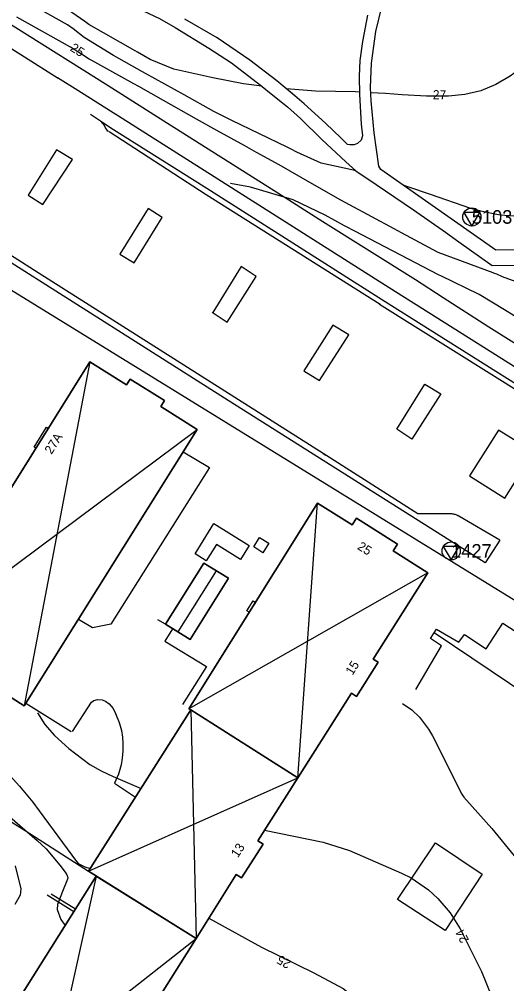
# Model space of a CAD drawing. Extents: x 67169 to 69652, y 20189 to 22818.
# Drawn here: x 69308.9 to 69362.6, y 21145.5 to 21251.9 of the extents above; entities that cross this region are included whole.
import ezdxf

# ---------------------------------------------------------------- set-up
doc = ezdxf.new("R2010")
doc.units = 0
for name, color, linetype in [('BYGGNAD_HUSLIV', 7, 'Continuous'), ('BYGGNAD_HUSLIV 11', 7, 'Continuous'), ('BYGGNAD_HUSLIV 13', 7, 'Continuous'), ('BYGGNADSDETALJER', 7, 'Continuous'), ('BYGGNADSSYMBOLER', 7, 'Continuous'), ('BYGGNADSSYMBOLER 30', 7, 'Continuous'), ('HOJDKURVOR_2014', 7, 'Continuous'), ('HOJDKURVOR_2014 5M', 7, 'Continuous'), ('HOJDKURVOR_TEXTER_2014', 7, 'Continuous'), ('Instruktioner', 7, 'Continuous'), ('MUR_STAKET', 7, 'Continuous'), ('MUR_STAKET_SYMBOL', 7, 'Continuous'), ('Std_Ritningsstämpel', 7, 'Continuous'), ('STOMPUNKTER', 7, 'Continuous'), ('STOMPUNKTER TEXT', 7, 'Continuous'), ('VAGAR 121', 7, 'Continuous'), ('VAGAR 123', 7, 'Continuous')]:
    doc.layers.add(name, color=color, linetype=linetype)

msp = doc.modelspace()

# ---------------------------------------------------------------- linework, layer by layer
at = {"layer": 'BYGGNAD_HUSLIV'}
for points in [[(69316.67, 21214.12), (69320.72, 21211.55), (69321.12, 21212.18), (69324.91, 21209.84), (69324.48, 21209.17), (69328.5, 21206.63), (69309.43, 21176.14), (69305.4, 21178.7), (69304.99, 21178.06), (69301.22, 21180.45), (69301.63, 21181.08), (69297.6, 21183.63), (69316.67, 21214.12)], [(69341.78, 21198.52), (69345.6, 21196.11), (69346.07, 21196.85), (69350.59, 21194), (69350.12, 21193.25), (69353.96, 21190.82), (69347.92, 21181.31), (69348.48, 21180.95), (69346.09, 21177.18), (69345.53, 21177.53), (69339.59, 21168.19), (69327.59, 21175.83), (69341.78, 21198.52)], [(69329.25, 21191.9), (69331.97, 21190.22), (69327.73, 21183.46), (69325.01, 21185.14), (69329.25, 21191.9)], [(69327.79, 21175.7), (69339.59, 21168.19), (69335.19, 21161.25), (69335.78, 21160.88), (69333.4, 21157.16), (69332.8, 21157.53), (69328.38, 21150.49), (69316.52, 21157.9), (69327.79, 21175.7)], [(69354.78, 21161.03), (69359.95, 21157.59), (69355.85, 21151.37), (69350.59, 21154.77), (69354.78, 21161.03)], [(69317.37, 21157.37), (69328.38, 21150.49), (69309.01, 21119.71), (69298, 21126.59), (69317.37, 21157.37)]]:
    msp.add_lwpolyline(points, dxfattribs=at)
at = {"layer": 'BYGGNAD_HUSLIV 11'}
for points in [[(69316.67, 21214.12), (69320.72, 21211.55), (69321.12, 21212.18), (69324.91, 21209.84), (69324.48, 21209.17), (69328.5, 21206.63), (69309.43, 21176.14), (69305.4, 21178.7), (69304.99, 21178.06), (69301.22, 21180.45), (69301.63, 21181.08), (69297.6, 21183.63), (69316.67, 21214.12)], [(69341.78, 21198.52), (69345.6, 21196.11), (69346.07, 21196.85), (69350.59, 21194), (69350.12, 21193.25), (69353.96, 21190.82), (69347.92, 21181.31), (69348.48, 21180.95), (69346.09, 21177.18), (69345.53, 21177.53), (69339.59, 21168.19), (69327.59, 21175.83), (69341.78, 21198.52)], [(69327.79, 21175.7), (69339.59, 21168.19), (69335.19, 21161.25), (69335.78, 21160.88), (69333.4, 21157.16), (69332.8, 21157.53), (69328.38, 21150.49), (69316.52, 21157.9), (69327.79, 21175.7)], [(69317.37, 21157.37), (69328.38, 21150.49), (69309.01, 21119.71), (69298, 21126.59), (69317.37, 21157.37)]]:
    msp.add_lwpolyline(points, dxfattribs=at)
at = {"layer": 'BYGGNAD_HUSLIV 13'}
msp.add_lwpolyline([(69354.78, 21161.03), (69359.95, 21157.59), (69355.85, 21151.37), (69350.59, 21154.77), (69354.78, 21161.03)], dxfattribs=at)
at = {"layer": 'BYGGNADSDETALJER'}
for points in [[(69311.89, 21206.89), (69312.07, 21206.77), (69310.69, 21204.56), (69310.51, 21204.69), (69311.89, 21206.89)], [(69334.66, 21187.72), (69334.92, 21187.55), (69334.25, 21186.47), (69333.99, 21186.64), (69334.66, 21187.72)]]:
    msp.add_lwpolyline(points, dxfattribs=at)
at = {"layer": 'BYGGNADSSYMBOLER'}
for p, q in [((69316.67, 21214.12), (69309.43, 21176.14)), ((69297.6, 21183.63), (69328.5, 21206.63)), ((69339.59, 21168.19), (69341.78, 21198.52)), ((69330.61, 21191.06), (69326.37, 21184.3)), ((69353.96, 21190.82), (69327.59, 21175.83)), ((69327.79, 21175.7), (69328.38, 21150.49)), ((69316.52, 21157.9), (69339.59, 21168.19)), ((69317.37, 21157.37), (69309.01, 21119.71)), ((69298, 21126.59), (69328.38, 21150.49))]:
    msp.add_line(p, q, dxfattribs=at)
at = {"layer": 'BYGGNADSSYMBOLER 30'}
for p, q in [((69316.67, 21214.12), (69309.43, 21176.14)), ((69297.6, 21183.63), (69328.5, 21206.63)), ((69339.59, 21168.19), (69341.78, 21198.52)), ((69353.96, 21190.82), (69327.59, 21175.83)), ((69327.79, 21175.7), (69328.38, 21150.49)), ((69316.52, 21157.9), (69339.59, 21168.19)), ((69317.37, 21157.37), (69309.01, 21119.71)), ((69298, 21126.59), (69328.38, 21150.49))]:
    msp.add_line(p, q, dxfattribs=at)
at = {"layer": 'HOJDKURVOR_2014'}
for points in [[(69335.63, 21244.51), (69333.62, 21244.76), (69330.22, 21245.44), (69325.91, 21246.41), (69323.33, 21247.47), (69321.93, 21248.26), (69321.65, 21248.41), (69316.55, 21251.33), (69316.42, 21251.42), (69316.1, 21251.65), (69312.4, 21254.27), (69310.31, 21255.68), (69308.89, 21256.76), (69308.21, 21257.35), (69307.56, 21257.95), (69304.51, 21260.93), (69302.71, 21262.76), (69302.54, 21262.88), (69302.5, 21262.91), (69300.81, 21263.85)], [(69381.94, 21256.01), (69381.31, 21254.25), (69380.17, 21251.12), (69379.36, 21248.94), (69378.59, 21247.16), (69377.05, 21244.2), (69376.13, 21242.54), (69374.1, 21239.33), (69372.98, 21237.78), (69369.48, 21233.17), (69368.27, 21231.9), (69366.81, 21230.91), (69365.18, 21230.31), (69363.44, 21230.17), (69361.91, 21230.3), (69359.75, 21230.72), (69358.7, 21231.03), (69354.22, 21232.57), (69351.72, 21233.42), (69351.21, 21233.59)], [(69345.99, 21235.17), (69345.57, 21235.29), (69342.19, 21236.04), (69339.51, 21237.23), (69338.79, 21237.6), (69338.43, 21237.78), (69332.33, 21240.74), (69330.35, 21241.74), (69327.06, 21243.56), (69322.8, 21245.92), (69322.47, 21246.1), (69319.26, 21247.91), (69316.03, 21249.88), (69314.82, 21250.86), (69314.18, 21251.29), (69309.86, 21253.7)], [(69370.87, 21253.3), (69368.55, 21250.41), (69367.25, 21248.82), (69366.66, 21248.26), (69363.04, 21245.63), (69361.45, 21244.7), (69359.8, 21243.99), (69358.04, 21243.59), (69356.21, 21243.41), (69353.8, 21243.42), (69351.1, 21243.55), (69349.28, 21243.71), (69347.64, 21243.8)], [(69346.4, 21243.87), (69345.97, 21243.9), (69341.55, 21243.98), (69338.36, 21244.23)], [(69379.42, 21220.12), (69378.06, 21218.64), (69375.99, 21216.98), (69374.03, 21215.74), (69373.17, 21215.43), (69372.25, 21215.32), (69371.31, 21215.34), (69369.42, 21215.81), (69367.68, 21216.63), (69364.54, 21218.52), (69362.39, 21219.84), (69359.62, 21221.55), (69355.39, 21223.59), (69355.2, 21223.68), (69346.67, 21228.12), (69346.03, 21228.45), (69344.76, 21229.12), (69342.6, 21230.29), (69339.09, 21231.96), (69334.4, 21233.36), (69332.16, 21233.77)], [(69295.71, 21181.6), (69297.15, 21181.02), (69298.29, 21180.35), (69298.93, 21179.61), (69299.74, 21178.09), (69299.97, 21177.53), (69300.17, 21176.97), (69302.96, 21168.37), (69303.08, 21168.09), (69303.42, 21167.7), (69310.86, 21161.3), (69311.83, 21160.38), (69313.34, 21158.58), (69313.95, 21157.8), (69314.13, 21157.5), (69314.22, 21157.19), (69314.21, 21157.03), (69313.63, 21155.67), (69313.08, 21154.22), (69313.05, 21153.66), (69313.46, 21152.57), (69313.93, 21151.91)], [(69351.14, 21176.42), (69352.17, 21175.72), (69353.03, 21174.89), (69354.03, 21173.56), (69354.45, 21172.84), (69357.68, 21166.39), (69357.91, 21166.07), (69360.99, 21162.6), (69363.45, 21159.58), (69365.62, 21156.34), (69366.81, 21154.33), (69368.23, 21151.54), (69369.61, 21148.32), (69370.61, 21145.49), (69371.02, 21143.74), (69372.34, 21136.55)], [(69310.87, 21175.38), (69311.71, 21174.08), (69312.76, 21172.88), (69314.33, 21171.44), (69316.66, 21169.69), (69317.92, 21168.97), (69319.24, 21168.34), (69322.31, 21167.04)], [(69335.94, 21162.44), (69342.41, 21161.09), (69345.32, 21160.2), (69351.05, 21157.68), (69352.09, 21157.16), (69354, 21155.85), (69355.05, 21154.89), (69356.41, 21153.31), (69357.51, 21151.54), (69359.86, 21146.83), (69360.97, 21144.13), (69361.93, 21141.58), (69362.23, 21140.63), (69362.51, 21137.47)], [(69308.41, 21158.5), (69309.05, 21155.95), (69308.97, 21155.26), (69308.37, 21154.24)]]:
    msp.add_lwpolyline(points, dxfattribs=at)
at = {"layer": 'HOJDKURVOR_2014 5M'}
for points in [[(69364.08, 21222.79), (69362.19, 21223.48), (69361.54, 21223.76), (69361.28, 21223.86), (69361.15, 21223.91), (69355.08, 21226.18), (69351.02, 21228.33), (69350.22, 21228.77), (69345.32, 21231.42), (69344.36, 21231.95), (69341.18, 21233.75), (69337.53, 21235.84), (69335.06, 21237.2), (69333.74, 21237.92), (69330.66, 21239.61), (69328.42, 21240.86), (69324.77, 21242.95), (69322.08, 21244.47), (69321.52, 21244.77), (69316.88, 21247.35), (69316.59, 21247.51), (69315.73, 21248.04), (69314.51, 21248.84), (69308.62, 21252.15)], [(69302.95, 21179.35), (69304.93, 21174.61), (69305.23, 21173.85), (69306.45, 21169.96), (69306.46, 21169.94), (69308.91, 21167.29), (69310.39, 21165.51), (69311.09, 21164.58), (69315.18, 21158.97), (69315.21, 21158.93), (69315.36, 21158.76), (69316.11, 21158.38), (69316.71, 21158.2)], [(69329.78, 21152.71), (69335.61, 21149.51), (69341.37, 21146.67), (69344.61, 21144.96), (69346.46, 21143.52), (69347.75, 21141.55), (69348.37, 21139.26), (69348.38, 21138.79)]]:
    msp.add_lwpolyline(points, dxfattribs=at)
at = {"layer": 'MUR_STAKET'}
for p, q in [((69354.64, 21184.24), (69386.51, 21162.78)), ((69309.61, 21176.43), (69314.61, 21173.3)), ((69319.37, 21167.61), (69321.69, 21166.06)), ((69311.95, 21155.31), (69314.91, 21153.46)), ((69312.41, 21155.42), (69315.09, 21153.75))]:
    msp.add_line(p, q, dxfattribs=at)
for points in [[(69296.1, 21258.84), (69302.52, 21254.78), (69308.5, 21251), (69318.67, 21244.59), (69325.22, 21240.45), (69336.99, 21232.99), (69342.36, 21229.57), (69352.6, 21223.18), (69355.62, 21221.19), (69360.68, 21217.97), (69370.52, 21211.77), (69376.01, 21208.27), (69380.2, 21208.31), (69385.38, 21216.32)], [(69284.59, 21177.99), (69309.53, 21162.41), (69316.52, 21157.9)]]:
    msp.add_lwpolyline(points, dxfattribs=at)
at = {"layer": 'MUR_STAKET_SYMBOL'}
for p, q in [((69310.26, 21249.89), (69310.26, 21249.89)), ((69311.94, 21248.83), (69311.94, 21248.83)), ((69313.61, 21247.78), (69313.61, 21247.78)), ((69315.37, 21246.67), (69315.37, 21246.67)), ((69317.12, 21245.57), (69317.12, 21245.57)), ((69318.93, 21244.43), (69318.93, 21244.43)), ((69320.48, 21243.44), (69320.48, 21243.44)), ((69322.13, 21242.4), (69322.13, 21242.4)), ((69323.97, 21241.24), (69323.97, 21241.24)), ((69325.57, 21240.23), (69325.57, 21240.23)), ((69327.34, 21239.1), (69327.34, 21239.1)), ((69329, 21238.05), (69329, 21238.05)), ((69330.67, 21236.99), (69330.67, 21236.99)), ((69332.4, 21235.89), (69332.4, 21235.89)), ((69334.16, 21234.78), (69334.16, 21234.78)), ((69335.82, 21233.73), (69335.82, 21233.73)), ((69337.42, 21232.71), (69337.42, 21232.71)), ((69339.16, 21231.61), (69339.16, 21231.61)), ((69340.85, 21230.53), (69340.85, 21230.53)), ((69342.51, 21229.48), (69342.51, 21229.48)), ((69344.24, 21228.4), (69344.24, 21228.4)), ((69345.96, 21227.33), (69345.96, 21227.33)), ((69347.5, 21226.36), (69347.5, 21226.36)), ((69349.37, 21225.2), (69349.37, 21225.2)), ((69351.09, 21224.12), (69351.09, 21224.12)), ((69352.75, 21223.08), (69352.75, 21223.08)), ((69354.34, 21222.04), (69354.34, 21222.04)), ((69356.02, 21220.94), (69356.02, 21220.94)), ((69357.69, 21219.88), (69357.69, 21219.88)), ((69357.69, 21219.88), (69357.69, 21219.88)), ((69359.39, 21218.79), (69359.39, 21218.79)), ((69361.03, 21217.75), (69361.03, 21217.75)), ((69310.89, 21175.62), (69310.89, 21175.62)), ((69312.11, 21174.86), (69312.11, 21174.86)), ((69313.34, 21174.09), (69313.34, 21174.09)), ((69314.61, 21173.3), (69314.61, 21173.3)), ((69319.37, 21167.61), (69319.37, 21167.61)), ((69320.53, 21166.83), (69320.53, 21166.83)), ((69321.69, 21166.06), (69321.69, 21166.06)), ((69312.7, 21160.37), (69312.7, 21160.37)), ((69312.34, 21155.07), (69312.34, 21155.07)), ((69313.43, 21154.39), (69313.43, 21154.39)), ((69314.38, 21153.79), (69314.38, 21153.79))]:
    msp.add_line(p, q, dxfattribs=at)
at = {"layer": 'Std_Ritningsstämpel'}
for points in [[(69316.67, 21214.12), (69297.6, 21183.63), (69301.63, 21181.08), (69301.22, 21180.45), (69304.99, 21178.06), (69305.4, 21178.7), (69309.43, 21176.14), (69328.5, 21206.63), (69324.48, 21209.17), (69324.91, 21209.84), (69321.12, 21212.18), (69320.72, 21211.55)], [(69341.78, 21198.52), (69327.59, 21175.83), (69327.79, 21175.7), (69339.59, 21168.19), (69345.53, 21177.53), (69346.09, 21177.18), (69348.48, 21180.95), (69347.92, 21181.31), (69353.96, 21190.82), (69350.12, 21193.25), (69350.59, 21194), (69346.07, 21196.85), (69345.6, 21196.11)], [(69329.25, 21191.9), (69325.01, 21185.14), (69327.73, 21183.46), (69331.97, 21190.22)], [(69327.79, 21175.7), (69316.52, 21157.9), (69328.38, 21150.49), (69332.8, 21157.53), (69333.4, 21157.16), (69335.78, 21160.88), (69335.19, 21161.25), (69339.59, 21168.19)], [(69317.37, 21157.37), (69298, 21126.59), (69309.01, 21119.71), (69328.38, 21150.49)]]:
    msp.add_lwpolyline(points, close=True, dxfattribs=at)
at = {"layer": 'STOMPUNKTER'}
for points in [[(69358.8, 21229.09), (69359.68, 21230.57), (69357.93, 21230.57)], [(69356.52, 21192.24), (69357.4, 21193.72), (69355.64, 21193.72)]]:
    msp.add_lwpolyline(points, close=True, dxfattribs=at)
for centre in [(69358.8, 21230.09), (69356.52, 21193.24)]:
    msp.add_circle(centre, 1, dxfattribs=at)
at = {"layer": 'VAGAR 121'}
for p, q in [((69376.14, 21179.98), (69264.59, 21248.76)), ((69310.95, 21223.94), (69278.89, 21244.25)), ((69331.52, 21210.09), (69298.62, 21230.97)), ((69342.38, 21204), (69310.95, 21223.94)), ((69360.26, 21191.94), (69331.52, 21210.09)), ((69361.87, 21194.41), (69360.26, 21191.94))]:
    msp.add_line(p, q, dxfattribs=at)
for points in [[(69313.16, 21245.38), (69298.29, 21254.81), (69295.63, 21256.45), (69293.87, 21257.57), (69257.76, 21280.45), (69248.82, 21286.11), (69242.96, 21289.82), (69226.82, 21300.08), (69172.15, 21334.79)], [(69414.59, 21194.78), (69411.91, 21193.25), (69407.79, 21192.49), (69397.41, 21194.85), (69395.42, 21195.53), (69393.83, 21196.08), (69391.92, 21196.78), (69390.97, 21197.16), (69390.07, 21197.55), (69387.93, 21198.57), (69386.03, 21199.75), (69373.67, 21207.5), (69365.5, 21212.31), (69349.69, 21222.27), (69330.77, 21234.25), (69319.82, 21241.2), (69318.93, 21241.75), (69315.32, 21244.04), (69313.08, 21245.43)], [(69369.56, 21206.71), (69370.36, 21207.75), (69366.63, 21210.06), (69364.73, 21210.97), (69348.94, 21220.92), (69329.56, 21233.23), (69318.96, 21239.89), (69317.84, 21240.64), (69316.75, 21241.39)], [(69369.56, 21206.71), (69370.36, 21207.75), (69366.63, 21210.06), (69364.73, 21210.97), (69348.94, 21220.92), (69329.56, 21233.23), (69318.96, 21239.89), (69317.84, 21240.64), (69316.75, 21241.39)], [(69318.74, 21239.51), (69318.66, 21239.57), (69318.58, 21239.65), (69318.49, 21239.77), (69318.39, 21239.92), (69318.26, 21240.17), (69318.17, 21240.31), (69318.07, 21240.45), (69317.98, 21240.53)], [(69348.67, 21220.42), (69329.5, 21232.52), (69318.81, 21239.47)], [(69313, 21237.49), (69309.86, 21232.49), (69311.48, 21231.45), (69314.75, 21236.43), (69313, 21237.49)], [(69323.08, 21231.01), (69319.98, 21226), (69321.54, 21225.03), (69324.64, 21230.04), (69323.08, 21231.01)], [(69330.16, 21219.58), (69331.81, 21218.48), (69335, 21223.53), (69333.34, 21224.62), (69330.21, 21219.56)], [(69348.61, 21220.46), (69364.64, 21210.44), (69365.99, 21208.98), (69369.56, 21206.71)], [(69343.48, 21218.16), (69340.28, 21213.12), (69342.01, 21212.04), (69345.22, 21217.08), (69343.48, 21218.16)], [(69353.61, 21211.63), (69355.36, 21210.59), (69352.17, 21205.57), (69350.53, 21206.67), (69353.61, 21211.63)], [(69361.73, 21206.58), (69358.55, 21201.51), (69362.43, 21199.07), (69365.62, 21204.15), (69361.73, 21206.58)], [(69326.95, 21204.16), (69329.85, 21202.44), (69318.99, 21185.15), (69316.97, 21184.76), (69315.4, 21185.68)], [(69352.85, 21197.34), (69342.38, 21204), (69342.7, 21203.79), (69342.64, 21203.84)], [(69361.87, 21194.41), (69357.37, 21197.06), (69357.31, 21197.1), (69357.25, 21197.12), (69357.14, 21197.18), (69357.05, 21197.21), (69356.96, 21197.24), (69356.88, 21197.27), (69356.81, 21197.28), (69356.69, 21197.31), (69356.59, 21197.32), (69356.52, 21197.33), (69356.42, 21197.34), (69356.32, 21197.34), (69352.85, 21197.34)], [(69330.35, 21196.26), (69334.22, 21193.82), (69333.27, 21192.3), (69330.62, 21193.93), (69329.48, 21192.14), (69328.28, 21192.93), (69330.35, 21196.26)], [(69335.37, 21194.72), (69336.41, 21194.09), (69335.76, 21193.04), (69334.74, 21193.68), (69335.37, 21194.72)], [(69352.61, 21177.94), (69355.46, 21182.77), (69354.22, 21183.59), (69354.89, 21184.61), (69357.37, 21183.18), (69357.97, 21184.03), (69360.36, 21182.45), (69362.23, 21185.27), (69366.4, 21182.55), (69367.48, 21181.85), (69371.15, 21179.29)]]:
    msp.add_lwpolyline(points, dxfattribs=at)
at = {"layer": 'VAGAR 123'}
msp.add_line((69325.01, 21185.14), (69324.15, 21185.65), dxfattribs=at)
for points in [[(69309.14, 21259), (69311.72, 21257.72), (69314.8, 21256.12), (69317.32, 21255.04), (69320.43, 21253.76), (69322.55, 21252.83), (69324.35, 21251.98), (69326.09, 21250.99), (69329.8, 21248.71), (69332.28, 21247.08), (69335.47, 21244.63), (69336.86, 21243.53), (69338.45, 21242.23), (69339.88, 21240.95), (69342.25, 21238.63), (69344.9, 21236.16), (69346.01, 21235.16), (69348.26, 21233.66), (69352.35, 21230.87), (69355.88, 21228.4), (69357.36, 21227.36), (69361.05, 21224.73), (69372.49, 21224.87)], [(69384.4, 21219.66), (69382.25, 21221.02), (69376.69, 21224.25), (69372.59, 21226.59), (69361.43, 21226.43), (69348.75, 21235.31), (69348.53, 21235.7), (69348.01, 21239.37), (69347.68, 21242.91), (69347.61, 21244.38), (69347.72, 21247.07), (69348.2, 21250.55), (69348.89, 21253.41), (69349.9, 21256.54), (69350.71, 21258.58), (69350.86, 21258.95)], [(69347.3, 21252.37), (69346.74, 21249.46), (69346.46, 21247.35), (69346.38, 21245.64), (69346.4, 21243.6), (69346.58, 21240.32), (69346.75, 21239.04), (69346.58, 21238.57), (69346.19, 21238.2), (69345.8, 21238.04), (69345.34, 21238.04), (69345.08, 21238.09), (69344.39, 21238.78), (69342.67, 21240.43), (69340.32, 21242.58), (69339.28, 21243.46), (69337.29, 21245.11), (69334.3, 21247.39), (69330.72, 21249.84), (69327.13, 21251.92)], [(69325.78, 21184.66), (69324.93, 21183.3), (69329.52, 21180.5), (69326.9, 21176.29)], [(69314.76, 21173.33), (69316.85, 21176.56), (69317.12, 21176.75), (69317.5, 21176.83), (69318.02, 21176.8), (69318.39, 21176.66), (69318.79, 21176.36), (69319.22, 21175.84), (69319.5, 21175.29), (69319.91, 21174.31), (69320.16, 21173.44), (69320.27, 21172.69), (69320.3, 21172), (69320.3, 21171.18), (69320.24, 21170.38), (69320.11, 21169.64), (69319.83, 21168.62), (69319.37, 21167.61)]]:
    msp.add_lwpolyline(points, dxfattribs=at)

# ---------------------------------------------------------------- texts
at = {"layer": 'HOJDKURVOR_TEXTER_2014'}
for s, rotation, p in [('25', 327.3491, (69314.4, 21248.5)), ('27', 359.7539, (69354.49, 21243.08)), ('24', 118, (69358.51, 21150.31)), ('25', 150, (69338.96, 21147.94))]:
    msp.add_text(s, height=1, rotation=rotation, dxfattribs=at).set_placement(p)
at = {"layer": 'Instruktioner'}
for s, rotation, p in [('27A', 57.8133, (69312.44, 21203.83)), ('25', 328.0515, (69346.09, 21193.49)), ('15', 57.6739, (69345.63, 21179.45)), ('13', 56.7218, (69332.98, 21159.32))]:
    msp.add_text(s, height=1, rotation=rotation, dxfattribs=at).set_placement(p)
at = {"layer": 'STOMPUNKTER TEXT'}
for s, p in [('5103', (69358.8, 21229.34)), ('1427', (69356.52, 21192.49))]:
    msp.add_text(s, height=1.5, dxfattribs=at).set_placement(p)

doc.saveas('drawing.dxf')
